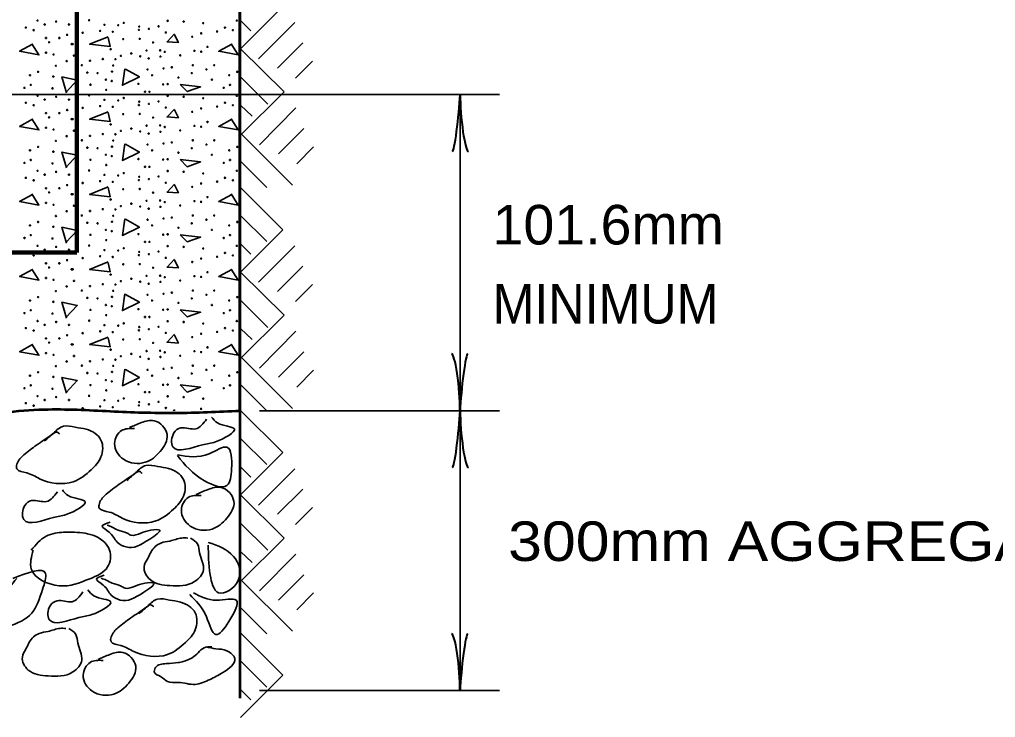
# Model space of a CAD drawing. Extents: x 442 to 1297, y -1132 to -588.
# Drawn here: x 662.4 to 721.6, y -999.4 to -957 of the extents above; entities that cross this region are included whole.
import ezdxf

# ---------------------------------------------------------------- set-up
doc = ezdxf.new("R2010")
doc.units = 0
doc.header["$LTSCALE"] = 0.96
doc.layers.add('1', color=7, linetype='Continuous', lineweight=35)

msp = doc.modelspace()

# ---------------------------------------------------------------- linework, layer by layer
at = {"layer": '1', "lineweight": 53}
for p, q in [((675.7476, -980.7675), (675.7476, -886.6076)), ((675.7476, -886.6076), (675.7476, -980.8522)), ((675.7476, -980.7675), (675.7476, -998.2092))]:
    msp.add_line(p, q, dxfattribs=at)
at = {"layer": '1', "lineweight": 106}
for p, q in [((665.8476, -971.1675), (665.8476, -893.8481)), ((579.7476, -971.1675), (665.8476, -971.1675))]:
    msp.add_line(p, q, dxfattribs=at)
at = {"layer": '1'}
for p, q in [((675.7956, -958.7835), (678.3636, -956.2155)), ((675.7956, -957.0795), (676.4196, -957.7035)), ((676.8756, -959.4075), (679.0836, -957.1995)), ((678.0276, -959.9595), (679.5636, -958.4235)), ((675.7956, -958.7835), (678.4356, -961.3995)), ((679.1316, -960.5835), (680.1636, -959.5515)), ((675.7956, -960.4875), (677.4516, -962.1435)), ((657.1476, -961.5675), (691.5175, -961.5675)), ((675.7956, -964.0395), (678.4356, -961.3995)), ((689.1175, -961.5675), (689.1175, -980.7675)), ((675.7956, -962.2155), (676.4916, -962.8875)), ((676.9476, -964.6155), (679.1556, -962.3835)), ((675.7956, -963.9195), (678.9396, -967.0635)), ((678.0996, -965.1675), (679.6356, -963.6315)), ((679.2036, -965.7675), (680.2116, -964.7355)), ((675.7956, -965.6235), (677.3796, -967.2075)), ((675.7956, -967.2075), (678.3636, -969.7755)), ((675.7956, -968.9115), (677.3796, -970.4955)), ((675.7956, -972.3435), (678.3636, -969.7755)), ((675.7956, -970.6395), (676.4196, -971.2635)), ((676.8756, -972.9675), (679.0836, -970.7595)), ((675.7956, -972.3435), (678.4356, -974.9595)), ((678.0276, -973.5195), (679.5636, -971.9835)), ((679.1316, -974.1435), (680.1636, -973.1115)), ((675.7956, -974.0475), (677.4516, -975.7035)), ((675.7956, -977.5995), (678.4356, -974.9595)), ((675.7956, -975.7755), (676.4916, -976.4475)), ((676.9476, -978.1755), (679.1556, -975.9435)), ((675.7956, -977.4795), (678.9396, -980.6235)), ((678.0996, -978.7275), (679.6356, -977.1915)), ((679.2036, -979.3275), (680.2116, -978.2955)), ((675.7956, -979.1835), (677.3796, -980.7675)), ((671.7818, -980.6867), (671.705, -980.7675)), ((671.7982, -980.7675), (671.7818, -980.7347)), ((675.7956, -980.7435), (678.3636, -983.3115)), ((676.9476, -980.7675), (691.5175, -980.7675)), ((689.1175, -980.7675), (689.1175, -997.758)), ((675.7956, -982.4475), (677.3796, -984.0315)), ((675.7956, -985.8795), (678.3636, -983.3115)), ((675.7956, -984.1755), (676.4196, -984.7995)), ((676.8756, -986.5035), (679.0836, -984.2955)), ((675.7956, -985.8795), (678.4356, -988.4955)), ((678.0276, -987.0555), (679.5636, -985.5195)), ((679.1316, -987.6795), (680.1636, -986.6475)), ((675.7956, -987.5835), (677.4516, -989.2395)), ((675.7956, -991.1355), (678.4356, -988.4955)), ((675.7956, -989.3115), (676.4916, -989.9835)), ((676.9476, -991.7115), (679.1556, -989.4795)), ((678.0996, -992.2635), (679.6356, -990.7275)), ((675.7956, -991.0155), (678.9396, -994.1595)), ((679.2036, -992.8635), (680.2116, -991.8315)), ((675.7956, -992.7195), (677.3796, -994.3035)), ((675.7956, -994.2555), (678.3636, -996.8235)), ((675.7956, -995.9595), (677.3796, -997.5435)), ((675.7956, -999.3915), (678.3636, -996.8235)), ((675.7956, -997.6875), (676.4196, -998.3115)), ((676.9476, -997.758), (691.5175, -997.758))]:
    msp.add_line(p, q, dxfattribs=at)
for points in [[(667.7498, -958.0547), (666.6218, -958.5107), (667.8698, -958.6547), (667.7498, -958.1027)], [(671.7818, -957.8867), (671.3258, -958.3667), (672.0218, -958.4147), (671.7818, -957.9347)], [(663.1658, -958.5107), (662.3738, -958.9427), (663.5498, -959.1587), (663.1178, -958.4867)], [(675.2618, -958.5107), (674.4698, -958.9427), (675.6458, -959.1587), (675.2138, -958.4867)], [(665.2298, -961.4627), (664.9418, -960.5027), (665.8778, -960.6947), (665.2058, -961.4147)], [(668.8058, -960.0227), (669.6458, -960.5027), (668.6138, -961.0067), (668.7578, -959.9987)], [(667.7498, -962.6147), (666.6218, -963.0707), (667.8698, -963.2147), (667.7498, -962.6627)], [(671.7818, -962.4467), (671.3258, -962.9267), (672.0218, -962.9747), (671.7818, -962.4947)], [(663.1658, -963.0707), (662.3738, -963.5027), (663.5498, -963.7187), (663.1178, -963.0467)], [(675.2618, -963.0707), (674.4698, -963.5027), (675.6458, -963.7187), (675.2138, -963.0467)], [(668.8058, -964.5827), (669.6458, -965.0627), (668.6138, -965.5667), (668.7578, -964.5587)], [(665.2298, -966.0227), (664.9418, -965.0627), (665.8778, -965.2547), (665.2058, -965.9747)], [(671.7818, -967.0067), (671.3258, -967.4867), (672.0218, -967.5347), (671.7818, -967.0547)], [(663.1658, -967.6307), (662.3738, -968.0627), (663.5498, -968.2787), (663.1178, -967.6067)], [(667.7498, -967.1747), (666.6218, -967.6307), (667.8698, -967.7747), (667.7498, -967.2227)], [(675.2618, -967.6307), (674.4698, -968.0627), (675.6458, -968.2787), (675.2138, -967.6067)], [(668.8058, -969.1427), (669.6458, -969.6227), (668.6138, -970.1267), (668.7578, -969.1187)], [(665.2298, -970.5827), (664.9418, -969.6227), (665.8778, -969.8147), (665.2058, -970.5347)], [(667.7498, -971.7347), (666.6218, -972.1907), (667.8698, -972.3347), (667.7498, -971.7827)], [(671.7818, -971.5667), (671.3258, -972.0467), (672.0218, -972.0947), (671.7818, -971.6147)], [(663.1658, -972.1907), (662.3738, -972.6227), (663.5498, -972.8387), (663.1178, -972.1667)], [(675.2618, -972.1907), (674.4698, -972.6227), (675.6458, -972.8387), (675.2138, -972.1667)], [(668.8058, -973.7027), (669.6458, -974.1827), (668.6138, -974.6867), (668.7578, -973.6787)], [(665.2298, -975.1427), (664.9418, -974.1827), (665.8778, -974.3747), (665.2058, -975.0947)], [(667.7498, -976.2947), (666.6218, -976.7507), (667.8698, -976.8947), (667.7498, -976.3427)], [(671.7818, -976.1267), (671.3258, -976.6067), (672.0218, -976.6547), (671.7818, -976.1747)], [(663.1658, -976.7507), (662.3738, -977.1827), (663.5498, -977.3987), (663.1178, -976.7267)], [(675.2618, -976.7507), (674.4698, -977.1827), (675.6458, -977.3987), (675.2138, -976.7267)], [(668.8058, -978.2627), (669.6458, -978.7427), (668.6138, -979.2467), (668.7578, -978.2387)], [(665.2298, -979.7027), (664.9418, -978.7427), (665.8778, -978.9347), (665.2058, -979.6547)]]:
    msp.add_lwpolyline(points, dxfattribs=at)
for points in [[(672.1178, -960.9587), (673.3658, -961.1027), (672.5498, -961.3907)], [(672.1178, -965.5187), (673.3658, -965.6627), (672.5498, -965.9507)], [(672.1178, -970.0787), (673.3658, -970.2227), (672.5498, -970.5107)], [(672.1178, -974.6387), (673.3658, -974.7827), (672.5498, -975.0707)], [(672.1178, -979.1987), (673.3658, -979.3427), (672.5498, -979.6307)]]:
    msp.add_lwpolyline(points, close=True, dxfattribs=at)
for centre in [(662.7508, -957.5057), (663.4664, -957.0762), (663.8958, -957.3149), (664.5956, -957.1398), (665.3749, -957.3149), (666.5995, -957.0602), (667.5219, -957.3307), (668.3648, -957.3625), (668.6988, -957.2194), (669.6371, -957.4421), (670.2255, -957.5795), (670.8139, -957.4261), (671.3638, -957.0921), (672.334, -957.1398), (673.5268, -957.2352), (674.8468, -957.5057), (675.5624, -957.0762), (663.2278, -957.659), (663.9753, -958.1362), (664.7864, -958.1362), (665.2636, -957.9453), (666.2018, -957.8181), (667.2674, -957.7067), (668.0308, -957.7545), (668.6669, -958.1999), (669.6212, -957.6431), (669.6689, -958.184), (671.2525, -957.8021), (672.8588, -958.0567), (673.3996, -957.8499), (674.3697, -957.7385), (675.3238, -957.659), (664.1662, -958.3908), (665.5339, -958.5021), (665.5975, -958.5021), (670.48, -958.4066), (673.7812, -958.6771), (663.9754, -959.0272), (664.4365, -959.1384), (665.6771, -959.2021), (667.9035, -958.8203), (668.5238, -959.2181), (669.1599, -959.0748), (669.7007, -959.2498), (670.0823, -958.8998), (670.2097, -959.3771), (670.9094, -958.8839), (670.9252, -959.2657), (671.1889, -958.9794), (672.1272, -959.1862), (672.986, -958.9158), (673.3996, -958.9635), (664.5797, -959.8226), (665.2317, -959.5362), (666.1542, -959.7907), (666.6472, -959.5203), (667.4265, -959.4089), (668.0626, -959.8066), (668.1898, -959.4248), (671.1161, -959.9816), (671.6182, -959.918), (672.8905, -959.7907), (674.1947, -959.7907), (663.0052, -960.3953), (663.4982, -960.1885), (664.4206, -960.4748), (666.4881, -960.2362), (667.1083, -960.268), (667.9831, -960.1725), (670.1459, -960.0452), (670.4164, -960.3953), (672.0159, -960.5385), (672.827, -960.268), (673.7176, -960.0452), (675.1012, -960.3953), (675.5942, -960.1885), (662.6712, -961.1589), (663.053, -960.9839), (666.6789, -960.968), (667.6173, -960.6658), (667.9672, -960.7453), (669.5893, -960.9203), (671.0925, -960.9548), (671.3638, -960.9361), (674.0515, -960.6658), (674.7672, -961.1589), (675.149, -960.9839), (663.4664, -961.6362), (664.3729, -961.1907), (664.5956, -961.6998), (666.5995, -961.6202), (667.6332, -961.2862), (669.987, -961.3976), (670.2573, -961.3976), (671.3638, -961.6521), (672.334, -961.6998), (675.5624, -961.6362), (662.7508, -962.0657), (663.2278, -962.219), (663.8958, -961.8749), (665.3749, -961.8749), (667.2674, -962.2667), (667.5219, -961.8907), (668.0308, -962.3145), (668.3648, -961.9225), (668.6988, -961.7794), (669.6212, -962.2031), (669.6371, -962.0021), (670.2255, -962.1395), (670.8139, -961.9861), (673.5268, -961.7952), (674.3697, -962.2985), (674.8468, -962.0657), (675.3238, -962.219), (663.9753, -962.6962), (664.7864, -962.6962), (665.2636, -962.5053), (666.2018, -962.3781), (668.6669, -962.7599), (669.6689, -962.744), (671.2525, -962.3621), (672.8588, -962.6167), (673.3996, -962.4099), (664.1662, -962.9508), (665.5339, -963.0621), (665.5975, -963.0621), (667.9035, -963.3803), (670.0823, -963.4598), (670.48, -962.9666), (670.9094, -963.4439), (672.986, -963.4758), (673.3996, -963.5235), (673.7812, -963.2371), (663.9754, -963.5872), (664.4365, -963.6984), (665.2317, -964.0962), (665.6771, -963.7621), (666.6472, -964.0803), (667.4265, -963.9689), (668.1898, -963.9848), (668.5238, -963.7781), (669.1599, -963.6348), (669.7007, -963.8098), (670.2097, -963.9371), (670.9252, -963.8257), (671.1889, -963.5394), (672.1272, -963.7462), (664.5797, -964.3826), (666.1542, -964.3507), (668.0626, -964.3666), (670.1459, -964.6052), (671.1161, -964.5416), (671.6182, -964.478), (672.8905, -964.3507), (673.7176, -964.6052), (674.1947, -964.3507), (663.0052, -964.9553), (663.4982, -964.7485), (664.4206, -965.0348), (666.4881, -964.7962), (667.1083, -964.828), (667.6173, -965.2258), (667.9672, -965.3053), (667.9831, -964.7325), (670.4164, -964.9553), (672.0159, -965.0985), (672.827, -964.828), (674.0515, -965.2258), (675.1012, -964.9553), (675.5942, -964.7485), (662.6712, -965.7189), (663.053, -965.5439), (664.3729, -965.7507), (666.6789, -965.528), (667.6332, -965.8462), (669.5893, -965.4803), (671.0925, -965.5148), (671.3638, -965.4961), (674.7672, -965.7189), (675.149, -965.5439), (663.4664, -966.1962), (663.8958, -966.4349), (664.5956, -966.2598), (665.3749, -966.4349), (666.5995, -966.1802), (667.5219, -966.4507), (668.3648, -966.4825), (668.6988, -966.3394), (669.987, -965.9576), (670.2573, -965.9576), (671.3638, -966.2121), (672.334, -966.2598), (673.5268, -966.3552), (675.5624, -966.1962), (662.7508, -966.6257), (663.2278, -966.779), (665.2636, -967.0653), (666.2018, -966.9381), (667.2674, -966.8267), (668.0308, -966.8745), (669.6212, -966.7631), (669.6371, -966.5621), (670.2255, -966.6995), (670.8139, -966.5461), (671.2525, -966.9221), (673.3996, -966.9699), (674.3697, -966.8585), (674.8468, -966.6257), (675.3238, -966.779), (663.9753, -967.2562), (664.1662, -967.5108), (664.7864, -967.2562), (665.5339, -967.6221), (665.5975, -967.6221), (668.6669, -967.3199), (669.6689, -967.304), (670.48, -967.5266), (672.8588, -967.1767), (663.9754, -968.1472), (664.4365, -968.2584), (667.9035, -967.9403), (669.1599, -968.1948), (670.0823, -968.0198), (670.9094, -968.0039), (671.1889, -968.0994), (672.986, -968.0358), (673.3996, -968.0835), (673.7812, -967.7971), (665.2317, -968.6562), (665.6771, -968.3221), (666.6472, -968.6403), (667.4265, -968.5289), (668.1898, -968.5448), (668.5238, -968.3381), (669.7007, -968.3698), (670.2097, -968.4971), (670.9252, -968.3857), (672.1272, -968.3062), (663.4982, -969.3085), (664.5797, -968.9426), (666.1542, -968.9107), (666.4881, -969.3562), (667.1083, -969.388), (667.9831, -969.2925), (668.0626, -968.9266), (670.1459, -969.1652), (671.1161, -969.1016), (671.6182, -969.038), (672.827, -969.388), (672.8905, -968.9107), (673.7176, -969.1652), (674.1947, -968.9107), (675.5942, -969.3085), (663.0052, -969.5153), (664.4206, -969.5948), (667.6173, -969.7858), (667.9672, -969.8653), (669.5893, -970.0403), (670.4164, -969.5153), (671.3638, -970.0561), (672.0159, -969.6585), (674.0515, -969.7858), (675.1012, -969.5153), (662.6712, -970.2789), (663.053, -970.1039), (664.3729, -970.3107), (666.6789, -970.088), (667.6332, -970.4062), (669.987, -970.5176), (670.2573, -970.5176), (671.0925, -970.0748), (674.7672, -970.2789), (675.149, -970.1039), (662.7508, -971.1857), (663.4664, -970.7562), (663.8958, -970.9949), (664.5956, -970.8198), (665.3749, -970.9949), (666.5995, -970.7402), (667.5219, -971.0107), (668.3648, -971.0425), (668.6988, -970.8994), (669.6371, -971.1221), (670.8139, -971.1061), (671.3638, -970.7721), (672.334, -970.8198), (673.5268, -970.9152), (674.8468, -971.1857), (675.5624, -970.7562), (663.2278, -971.339), (663.9753, -971.8162), (664.7864, -971.8162), (665.2636, -971.6253), (666.2018, -971.4981), (667.2674, -971.3867), (668.0308, -971.4345), (669.6212, -971.3231), (670.2255, -971.2595), (671.2525, -971.4821), (672.8588, -971.7367), (673.3996, -971.5299), (674.3697, -971.4185), (675.3238, -971.339), (664.1662, -972.0708), (665.5339, -972.1821), (665.5975, -972.1821), (668.6669, -971.8799), (669.6689, -971.864), (670.48, -972.0866), (673.7812, -972.3571), (663.9754, -972.7072), (664.4365, -972.8184), (665.6771, -972.8821), (667.9035, -972.5003), (668.5238, -972.8981), (669.1599, -972.7548), (669.7007, -972.9298), (670.0823, -972.5798), (670.9094, -972.5639), (670.9252, -972.9457), (671.1889, -972.6594), (672.1272, -972.8662), (672.986, -972.5958), (673.3996, -972.6435), (664.5797, -973.5026), (665.2317, -973.2162), (666.1542, -973.4707), (666.6472, -973.2003), (667.4265, -973.0889), (668.0626, -973.4866), (668.1898, -973.1048), (670.2097, -973.0571), (671.6182, -973.598), (672.8905, -973.4707), (674.1947, -973.4707), (663.0052, -974.0753), (663.4982, -973.8685), (664.4206, -974.1548), (666.4881, -973.9162), (667.1083, -973.948), (667.9831, -973.8525), (670.1459, -973.7252), (670.4164, -974.0753), (671.1161, -973.6616), (672.827, -973.948), (673.7176, -973.7252), (675.1012, -974.0753), (675.5942, -973.8685), (663.053, -974.6639), (666.6789, -974.648), (667.6173, -974.3458), (667.9672, -974.4253), (669.5893, -974.6003), (671.0925, -974.6348), (671.3638, -974.6161), (672.0159, -974.2185), (674.0515, -974.3458), (675.149, -974.6639), (662.6712, -974.8389), (663.4664, -975.3162), (664.3729, -974.8707), (664.5956, -975.3798), (666.5995, -975.3002), (667.6332, -974.9662), (669.987, -975.0776), (670.2573, -975.0776), (671.3638, -975.3321), (672.334, -975.3798), (674.7672, -974.8389), (675.5624, -975.3162), (662.7508, -975.7457), (663.2278, -975.899), (663.8958, -975.5549), (665.3749, -975.5549), (667.2674, -975.9467), (667.5219, -975.5707), (668.3648, -975.6025), (668.6988, -975.4594), (669.6212, -975.8831), (669.6371, -975.6821), (670.2255, -975.8195), (670.8139, -975.6661), (673.5268, -975.4752), (674.3697, -975.9785), (674.8468, -975.7457), (675.3238, -975.899), (663.9753, -976.3762), (664.7864, -976.3762), (665.2636, -976.1853), (666.2018, -976.0581), (668.0308, -975.9945), (668.6669, -976.4399), (669.6689, -976.424), (671.2525, -976.0421), (672.8588, -976.2967), (673.3996, -976.0899), (664.1662, -976.6308), (665.5339, -976.7421), (665.5975, -976.7421), (667.9035, -977.0603), (670.0823, -977.1398), (670.48, -976.6466), (670.9094, -977.1239), (672.986, -977.1558), (673.7812, -976.9171), (663.9754, -977.2672), (664.4365, -977.3784), (665.6771, -977.4421), (666.6472, -977.7603), (667.4265, -977.6489), (668.1898, -977.6648), (668.5238, -977.4581), (669.1599, -977.3148), (669.7007, -977.4898), (670.2097, -977.6171), (670.9252, -977.5057), (671.1889, -977.2194), (672.1272, -977.4262), (673.3996, -977.2035), (664.5797, -978.0626), (665.2317, -977.7762), (666.1542, -978.0307), (668.0626, -978.0466), (670.1459, -978.2852), (671.1161, -978.2216), (671.6182, -978.158), (672.8905, -978.0307), (673.7176, -978.2852), (674.1947, -978.0307), (663.0052, -978.6353), (663.4982, -978.4285), (664.4206, -978.7148), (666.4881, -978.4762), (667.1083, -978.508), (667.6173, -978.9058), (667.9831, -978.4125), (670.4164, -978.6353), (672.0159, -978.7785), (672.827, -978.508), (674.0515, -978.9058), (675.1012, -978.6353), (675.5942, -978.4285), (662.6712, -979.3989), (663.053, -979.2239), (664.3729, -979.4307), (666.6789, -979.208), (667.6332, -979.5262), (667.9672, -978.9853), (669.5893, -979.1603), (671.0925, -979.1948), (671.3638, -979.1761), (674.7672, -979.3989), (675.149, -979.2239), (663.4664, -979.8762), (663.8958, -980.1149), (664.5956, -979.9398), (665.3749, -980.1149), (666.5995, -979.8602), (667.5219, -980.1307), (668.6988, -980.0194), (669.987, -979.6376), (670.2573, -979.6376), (671.3638, -979.8921), (672.334, -979.9398), (673.5268, -980.0352), (662.7508, -980.3057), (663.2278, -980.459), (666.2018, -980.6181), (667.2674, -980.5067), (668.0308, -980.5545), (668.3648, -980.1625), (669.6212, -980.4431), (669.6371, -980.2421), (670.2255, -980.3795), (670.8139, -980.2261), (671.2525, -980.6021), (673.3996, -980.6499)]:
    msp.add_circle(centre, 0.0318, dxfattribs=at)
msp.add_arc((665.2636, -980.7453), 0.0318, 315.56314, 224.43686, dxfattribs=at)
at = {"layer": '1', "lineweight": 40}
for centre, major_axis, ratio, start_param, end_param in [((688.8636, -962.9121), (0.2108, 2.1077), 0.07063, 3.1407148, 5.41811), ((688.8636, -962.9121), (0.2108, 2.1077), 0.07063, 3.1407148, 5.41811), ((689.4491, -962.8769), (-0.1874, 2.1428), 0.122415, 0.8963533, 3.1415927), ((689.4491, -962.8769), (-0.1874, 2.1428), 0.122415, 0.8963533, 3.1415927), ((688.7859, -979.4581), (0.1874, -2.1428), 0.122415, 0.8963533, 3.1415927), ((689.3714, -979.4229), (-0.2108, -2.1077), 0.07063, 3.1407148, 5.41811), ((688.8636, -982.1121), (0.2108, 2.1077), 0.07063, 3.1407148, 5.41811), ((689.4491, -982.0769), (-0.1874, 2.1428), 0.122415, 0.8963533, 3.1415927), ((688.7859, -996.4486), (0.1874, -2.1428), 0.122415, 0.8963533, 3.1415927), ((689.3714, -996.4134), (-0.2108, -2.1077), 0.07063, 3.1407148, 5.41811)]:
    msp.add_ellipse(centre, major_axis=major_axis, ratio=ratio, start_param=start_param, end_param=end_param, dxfattribs=at)
at = {"layer": '1', "lineweight": 53}
msp.add_spline([(570.1476, -980.7675), (572.0496, -980.6901), (574.8408, -980.8969), (575.7712, -981.3106), (578.1489, -981.2071), (580.3199, -981.0003), (583.0077, -981.0003), (586.0057, -980.8969), (587.0395, -980.7935), (590.0375, -981.2071), (593.0355, -981.1037), (594.6895, -981.1037), (598.928, -981.3106), (600.9956, -981.0003), (602.3395, -980.5867), (605.3375, -980.7935), (607.1983, -981.0003), (612.3673, -981.414), (614.2281, -981.3106), (617.2261, -981.0003), (619.2937, -980.7935), (623.739, -981.5174), (624.9795, -981.0003), (626.7369, -980.6901), (630.2518, -980.6901), (634.5937, -980.4833), (641.0032, -980.4833), (645.4485, -980.5867), (649.3769, -981.414), (652.0647, -981.414), (655.8898, -981.0003), (658.9911, -981.0003), (663.8499, -980.6901), (667.8817, -980.7935), (671.8101, -980.8969), (675.7476, -980.7675)], degree=3, dxfattribs=at)
at = {"layer": '1'}
for points in [[(673.7287, -981.2686), (673.067, -981.8701), (672.1648, -981.81), (671.7438, -982.1107), (671.6836, -982.9528), (673.4881, -982.8325), (674.27, -982.6521), (675.4128, -981.8701), (674.3903, -981.5092), (674.0294, -981.1483)], [(664.79, -982.1887), (664.6697, -982.0684), (664.3689, -982.1887), (663.4066, -982.8503), (662.6246, -983.4518), (662.384, -983.6924), (662.2036, -984.2939), (662.8051, -984.5345), (663.587, -984.8954), (665.6321, -985.0758), (666.7147, -984.354), (667.3162, -983.5721), (667.3162, -982.5496), (666.414, -981.8879), (665.7524, -981.7677), (665.0306, -981.7075), (664.4291, -982.1285), (663.8877, -982.6097)], [(669.3462, -981.8515), (668.5642, -981.9718), (668.1432, -982.7538), (668.6845, -983.7161), (670.0078, -983.8966), (670.91, -983.2349), (671.3311, -982.2124), (670.5491, -981.3703), (669.7672, -981.4906), (669.0454, -981.7914)], [(671.9653, -983.4371), (673.8893, -983.3805), (674.9645, -982.9842), (675.2474, -984.2862), (674.9645, -985.3051), (673.6064, -985.0221), (671.9653, -983.4937)], [(669.7971, -984.5738), (669.6768, -984.4535), (669.376, -984.5738), (668.4137, -985.2354), (667.6317, -985.8369), (667.3911, -986.0775), (667.2107, -986.679), (667.8122, -986.9196), (668.5941, -987.2805), (670.6392, -987.4609), (671.7218, -986.7391), (672.3233, -985.9572), (672.3233, -984.9347), (671.4211, -984.273), (670.7595, -984.1528), (670.0377, -984.0926), (669.4362, -984.5136), (668.8948, -984.9948)], [(673.3997, -985.9063), (672.6177, -986.0266), (672.1967, -986.8086), (672.738, -987.7709), (674.0613, -987.9514), (674.9635, -987.2897), (675.3846, -986.2672), (674.6026, -985.4251), (673.8207, -985.5454), (673.0989, -985.8462)], [(664.6683, -985.681), (664.0066, -986.2825), (663.1044, -986.2224), (662.6834, -986.5231), (662.6232, -987.3652), (664.4277, -987.2449), (665.2096, -987.0645), (666.3524, -986.2825), (665.3299, -985.9216), (664.969, -985.5607)], [(667.8739, -987.5354), (667.3927, -987.776), (667.8138, -988.1369), (668.295, -988.7384), (668.8363, -989.0391), (670.2799, -988.5579), (670.8814, -988.0166), (670.34, -988.0166), (669.7385, -988.197), (669.1371, -988.3173), (668.8965, -988.197), (668.3551, -988.0166), (667.9942, -987.8361), (667.6935, -987.7158)], [(663.2056, -989.2258), (663.0853, -990.3686), (664.7695, -991.3912), (666.6341, -990.9701), (667.7168, -990.2483), (667.8371, -989.2258), (666.8146, -988.3236), (665.5514, -988.1431), (664.5289, -988.2033), (663.9876, -988.3837), (663.0853, -989.2258)], [(672.5786, -988.4973), (672.2177, -988.4973), (671.4959, -988.6777), (670.9545, -988.798), (670.3531, -989.3394), (670.1726, -989.7003), (669.932, -990.2416), (670.2929, -991.0235), (671.4959, -991.3844), (672.9996, -991.1438), (673.5409, -990.4221), (673.3003, -989.3995), (673.1801, -988.8582), (672.759, -988.4973)], [(673.8327, -988.7582), (675.3606, -989.6073), (675.6436, -991.0791), (674.4552, -991.815), (673.9459, -990.7394), (673.8327, -988.928)], [(662.206, -990.9512), (660.8828, -993.4775), (660.9429, -993.9587), (661.6045, -993.8985), (663.1083, -993.0565), (663.7699, -991.6129), (663.9503, -990.6505), (661.9654, -990.9512)], [(667.5163, -990.7553), (667.0351, -990.9959), (667.4562, -991.3568), (667.9374, -991.9583), (668.4787, -992.259), (669.9223, -991.7778), (670.5238, -991.2365), (669.9824, -991.2365), (669.3809, -991.4169), (668.7795, -991.5372), (668.5389, -991.4169), (667.9975, -991.2365), (667.6366, -991.056), (667.3359, -990.9357)], [(666.2181, -991.7631), (665.5564, -992.3646), (664.6542, -992.3045), (664.2332, -992.6052), (664.173, -993.4473), (665.9775, -993.327), (666.7594, -993.1466), (667.9022, -992.3646), (666.8797, -992.0037), (666.5188, -991.6428)], [(672.9273, -991.815), (674.342, -992.2678), (675.5304, -992.2678), (675.0777, -993.5698), (674.2854, -994.3623), (673.7195, -993.2868), (672.7009, -991.9282)], [(670.5124, -992.6832), (670.3921, -992.5629), (670.0913, -992.6832), (669.129, -993.3448), (668.347, -993.9463), (668.1064, -994.1869), (667.926, -994.7884), (668.5275, -995.029), (669.3094, -995.3899), (671.3545, -995.5703), (672.4371, -994.8485), (673.0386, -994.0666), (673.0386, -993.0441), (672.1364, -992.3824), (671.4748, -992.2622), (670.753, -992.202), (670.1515, -992.623), (669.6101, -993.1042)], [(665.1872, -993.9831), (664.8263, -993.9831), (664.1045, -994.1635), (663.5631, -994.2838), (662.9617, -994.8252), (662.7812, -995.1861), (662.5406, -995.7274), (662.9015, -996.5093), (664.1045, -996.8702), (665.6082, -996.6296), (666.1495, -995.9079), (665.9089, -994.8853), (665.7887, -994.344), (665.3676, -993.9831)], [(667.4388, -995.9238), (666.6568, -996.0441), (666.2358, -996.8261), (666.7771, -997.7884), (668.1004, -997.9689), (669.0026, -997.3072), (669.4237, -996.2847), (668.6417, -995.4426), (667.8598, -995.5629), (667.138, -995.8637)], [(674.0556, -995.0982), (673.5744, -995.1584), (673.2136, -995.4591), (672.8527, -995.7599), (672.3113, -996.0004), (672.0106, -996.0606), (671.2888, -996.1207), (670.6272, -996.3613), (670.567, -996.6621), (670.9279, -996.9027), (671.3489, -997.2034), (672.0106, -997.2636), (673.0331, -997.3839), (673.9353, -997.0831), (674.7173, -996.6621), (675.4391, -995.82), (674.9579, -995.3388), (674.2962, -995.2185), (673.6947, -995.0982)]]:
    msp.add_spline(points, degree=3, dxfattribs=at)

# ---------------------------------------------------------------- texts
for s, width, p in [('101.6mm', 1.05, (691.0896, -970.6717)), ('MINIMUM', 0.95, (691.0896, -975.4717)), ('300mm AGGREGATE', 1.15, (692.0352, -989.8885))]:
    msp.add_text(s, height=2.4, dxfattribs=dict(at, width=width)).set_placement(p)

doc.saveas('drawing.dxf')
